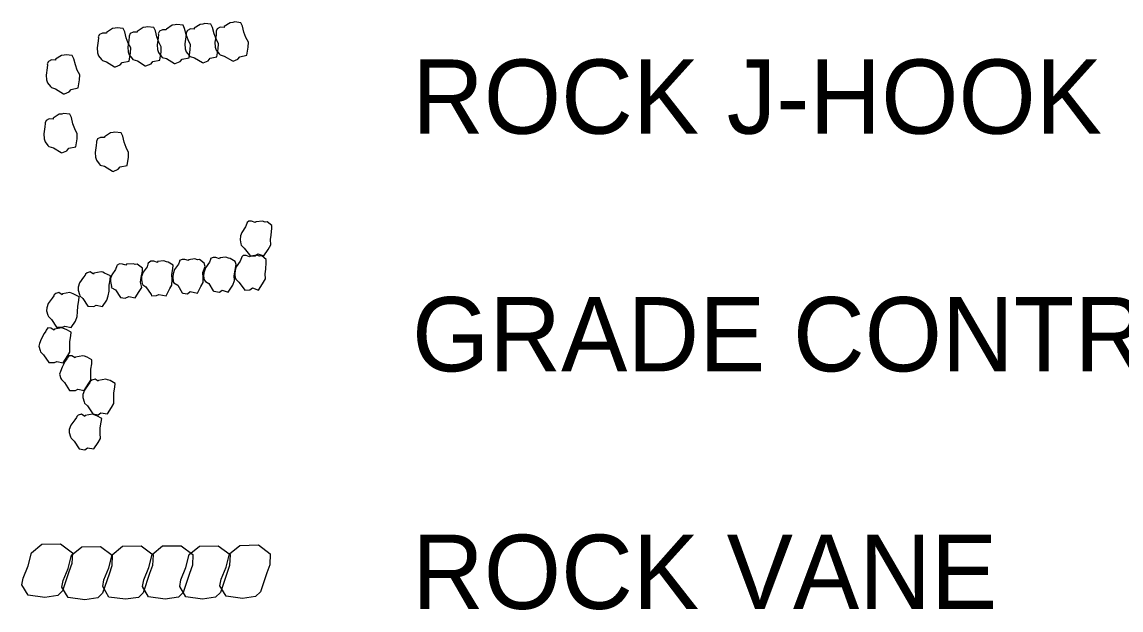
# Model space of a CAD drawing. Extents: x 1577194 to 26153757, y 723342 to 3772486.
# Drawn here: x 1577324.3 to 1577435.2, y 724614.4 to 724673.8 of the extents above; entities that cross this region are included whole.
import ezdxf

# ---------------------------------------------------------------- set-up
doc = ezdxf.new("R2010")
doc.units = 0
doc.layers.add('L-CL', color=7, linetype='Continuous')

msp = doc.modelspace()

# ---------------------------------------------------------------- linework, layer by layer
at = {"layer": 'L-CL'}
for p, q in [((1577339.66, 724669.6), (1577339.73, 724669.58)), ((1577342.48, 724669.68), (1577342.55, 724669.66)), ((1577345.5, 724669.85), (1577345.57, 724669.83)), ((1577333.62, 724669.27), (1577333.69, 724669.25)), ((1577336.71, 724669.37), (1577336.78, 724669.35)), ((1577328.47, 724666.54), (1577328.54, 724666.52)), ((1577328.23, 724660.6), (1577328.3, 724660.58)), ((1577333.41, 724658.73), (1577333.48, 724658.7)), ((1577347.24, 724650.26), (1577347.3, 724650.15)), ((1577337.29, 724646.26), (1577337.34, 724646.14)), ((1577340.42, 724646.44), (1577340.51, 724646.41)), ((1577343.55, 724646.63), (1577343.64, 724646.6)), ((1577346.69, 724646.81), (1577346.75, 724646.69)), ((1577330.92, 724645.07), (1577330.92, 724645.07)), ((1577334.21, 724645.95), (1577334.21, 724645.95)), ((1577327.76, 724642.97), (1577327.76, 724642.97)), ((1577326.96, 724639.39), (1577326.96, 724639.39)), ((1577329.07, 724636.58), (1577329.07, 724636.58)), ((1577331.4, 724634.22), (1577331.4, 724634.22)), ((1577330.04, 724630.68), (1577330.04, 724630.68))]:
    msp.add_line(p, q, dxfattribs=at)
for points in [[(1577333.69, 724669.25), (1577334.19, 724669.45), (1577334.39, 724669.7), (1577335.09, 724669.84), (1577335.21, 724670.67), (1577335.24, 724671.16), (1577334.99, 724671.66), (1577334.79, 724672.18), (1577334.64, 724672.8), (1577334.48, 724673.13), (1577333.86, 724673.21), (1577333.67, 724673.16), (1577333.39, 724673.13), (1577332.79, 724672.74), (1577332.78, 724672.65), (1577332.4, 724672.67), (1577332.1, 724672.52), (1577331.97, 724672.27), (1577331.98, 724672.19), (1577331.96, 724671.87), (1577331.85, 724671.16), (1577331.89, 724670.67), (1577331.99, 724670.36), (1577332.28, 724669.99), (1577332.38, 724669.89), (1577332.81, 724669.76), (1577333.62, 724669.27)], [(1577336.78, 724669.35), (1577337.29, 724669.55), (1577337.48, 724669.8), (1577338.18, 724669.94), (1577338.3, 724670.76), (1577338.33, 724671.26), (1577338.09, 724671.75), (1577337.89, 724672.28), (1577337.73, 724672.9), (1577337.57, 724673.23), (1577336.95, 724673.31), (1577336.77, 724673.26), (1577336.49, 724673.22), (1577335.89, 724672.84), (1577335.88, 724672.75), (1577335.49, 724672.77), (1577335.2, 724672.62), (1577335.07, 724672.37), (1577335.08, 724672.28), (1577335.06, 724671.96), (1577334.95, 724671.25), (1577334.98, 724670.77), (1577335.09, 724670.46), (1577335.37, 724670.09), (1577335.47, 724669.98), (1577335.91, 724669.86), (1577336.71, 724669.37)], [(1577339.73, 724669.58), (1577340.24, 724669.78), (1577340.43, 724670.03), (1577341.14, 724670.17), (1577341.25, 724670.99), (1577341.28, 724671.49), (1577341.04, 724671.98), (1577340.84, 724672.51), (1577340.68, 724673.13), (1577340.52, 724673.46), (1577339.9, 724673.54), (1577339.72, 724673.49), (1577339.44, 724673.46), (1577338.84, 724673.07), (1577338.83, 724672.98), (1577338.44, 724673), (1577338.15, 724672.85), (1577338.02, 724672.6), (1577338.03, 724672.52), (1577338.01, 724672.2), (1577337.9, 724671.49), (1577337.93, 724671), (1577338.04, 724670.69), (1577338.32, 724670.32), (1577338.42, 724670.21), (1577338.86, 724670.09), (1577339.66, 724669.6)], [(1577342.55, 724669.66), (1577343.05, 724669.86), (1577343.25, 724670.12), (1577343.95, 724670.25), (1577344.07, 724671.08), (1577344.1, 724671.58), (1577343.85, 724672.07), (1577343.65, 724672.6), (1577343.5, 724673.22), (1577343.34, 724673.55), (1577342.72, 724673.62), (1577342.53, 724673.58), (1577342.25, 724673.54), (1577341.65, 724673.16), (1577341.64, 724673.07), (1577341.26, 724673.08), (1577340.96, 724672.94), (1577340.83, 724672.69), (1577340.84, 724672.6), (1577340.82, 724672.28), (1577340.71, 724671.57), (1577340.75, 724671.09), (1577340.85, 724670.78), (1577341.14, 724670.4), (1577341.24, 724670.3), (1577341.67, 724670.17), (1577342.48, 724669.68)], [(1577345.57, 724669.83), (1577346.07, 724670.03), (1577346.27, 724670.28), (1577346.97, 724670.42), (1577347.09, 724671.24), (1577347.12, 724671.74), (1577346.87, 724672.23), (1577346.67, 724672.76), (1577346.52, 724673.38), (1577346.36, 724673.71), (1577345.74, 724673.79), (1577345.55, 724673.74), (1577345.28, 724673.71), (1577344.67, 724673.32), (1577344.67, 724673.23), (1577344.28, 724673.25), (1577343.98, 724673.1), (1577343.85, 724672.85), (1577343.86, 724672.77), (1577343.85, 724672.45), (1577343.73, 724671.74), (1577343.77, 724671.25), (1577343.87, 724670.94), (1577344.16, 724670.57), (1577344.26, 724670.46), (1577344.69, 724670.34), (1577345.5, 724669.85)], [(1577328.54, 724666.52), (1577329.04, 724666.73), (1577329.24, 724666.98), (1577329.94, 724667.12), (1577330.06, 724667.94), (1577330.09, 724668.44), (1577329.84, 724668.93), (1577329.65, 724669.46), (1577329.49, 724670.08), (1577329.33, 724670.41), (1577328.71, 724670.48), (1577328.52, 724670.43), (1577328.25, 724670.4), (1577327.65, 724670.02), (1577327.64, 724669.93), (1577327.25, 724669.95), (1577326.95, 724669.8), (1577326.82, 724669.55), (1577326.83, 724669.46), (1577326.82, 724669.14), (1577326.7, 724668.43), (1577326.74, 724667.95), (1577326.85, 724667.64), (1577327.13, 724667.26), (1577327.23, 724667.16), (1577327.66, 724667.03), (1577328.47, 724666.54)], [(1577328.3, 724660.58), (1577328.8, 724660.78), (1577329, 724661.03), (1577329.7, 724661.17), (1577329.82, 724661.99), (1577329.85, 724662.49), (1577329.61, 724662.99), (1577329.41, 724663.51), (1577329.25, 724664.13), (1577329.09, 724664.46), (1577328.47, 724664.54), (1577328.28, 724664.49), (1577328.01, 724664.46), (1577327.41, 724664.07), (1577327.4, 724663.98), (1577327.01, 724664), (1577326.71, 724663.85), (1577326.59, 724663.6), (1577326.59, 724663.52), (1577326.58, 724663.2), (1577326.47, 724662.49), (1577326.5, 724662), (1577326.61, 724661.69), (1577326.89, 724661.32), (1577326.99, 724661.22), (1577327.43, 724661.09), (1577328.23, 724660.6)], [(1577333.48, 724658.7), (1577333.98, 724658.91), (1577334.18, 724659.16), (1577334.88, 724659.3), (1577335, 724660.12), (1577335.03, 724660.62), (1577334.79, 724661.11), (1577334.59, 724661.64), (1577334.43, 724662.26), (1577334.27, 724662.59), (1577333.65, 724662.66), (1577333.47, 724662.61), (1577333.19, 724662.58), (1577332.59, 724662.2), (1577332.58, 724662.11), (1577332.19, 724662.12), (1577331.9, 724661.98), (1577331.77, 724661.73), (1577331.78, 724661.64), (1577331.76, 724661.32), (1577331.65, 724660.61), (1577331.68, 724660.13), (1577331.79, 724659.82), (1577332.07, 724659.45), (1577332.17, 724659.34), (1577332.61, 724659.21), (1577333.41, 724658.73)], [(1577347.3, 724650.15), (1577347.8, 724650.17), (1577348.07, 724650.37), (1577348.69, 724650.15), (1577349.11, 724650.8), (1577349.38, 724651.29), (1577349.36, 724651.8), (1577349.43, 724652.27), (1577349.47, 724652.95), (1577349.47, 724653.24), (1577349.01, 724653.6), (1577348.8, 724653.58), (1577348.54, 724653.67), (1577347.91, 724653.59), (1577347.79, 724653.53), (1577347.44, 724653.66), (1577347.15, 724653.66), (1577347, 724653.52), (1577346.97, 724653.43), (1577346.84, 724653.08), (1577346.45, 724652.52), (1577346.33, 724652.17), (1577346.29, 724651.79), (1577346.34, 724651.37), (1577346.4, 724651.25), (1577346.69, 724650.95), (1577347.24, 724650.26)], [(1577337.34, 724646.14), (1577337.85, 724646.16), (1577338.08, 724646.27), (1577338.82, 724646.11), (1577339.19, 724646.87), (1577339.4, 724647.2), (1577339.41, 724647.79), (1577339.39, 724648.29), (1577339.48, 724648.85), (1577339.52, 724649.23), (1577339.02, 724649.51), (1577338.85, 724649.57), (1577338.58, 724649.66), (1577337.96, 724649.58), (1577337.93, 724649.49), (1577337.58, 724649.62), (1577337.28, 724649.62), (1577337.01, 724649.42), (1577336.98, 724649.33), (1577336.89, 724649.07), (1577336.5, 724648.51), (1577336.34, 724648.07), (1577336.34, 724647.78), (1577336.39, 724647.36), (1577336.45, 724647.24), (1577336.77, 724647.03), (1577337.29, 724646.26)], [(1577340.51, 724646.41), (1577340.98, 724646.34), (1577341.25, 724646.55), (1577341.98, 724646.39), (1577342.32, 724647.06), (1577342.56, 724647.47), (1577342.54, 724647.97), (1577342.52, 724648.48), (1577342.74, 724649.09), (1577342.65, 724649.42), (1577342.19, 724649.78), (1577341.98, 724649.75), (1577341.72, 724649.85), (1577341.09, 724649.77), (1577341.06, 724649.68), (1577340.71, 724649.8), (1577340.42, 724649.81), (1577340.18, 724649.69), (1577340.15, 724649.61), (1577340.05, 724649.34), (1577339.66, 724648.79), (1577339.51, 724648.35), (1577339.5, 724648.05), (1577339.52, 724647.55), (1577339.58, 724647.43), (1577339.99, 724647.19), (1577340.42, 724646.44)], [(1577343.64, 724646.6), (1577344.2, 724646.5), (1577344.47, 724646.7), (1577345.09, 724646.48), (1577345.54, 724647.22), (1577345.7, 724647.66), (1577345.68, 724648.16), (1577345.77, 724648.72), (1577345.87, 724649.28), (1577345.79, 724649.6), (1577345.29, 724649.88), (1577345.11, 724649.94), (1577344.85, 724650.03), (1577344.23, 724649.95), (1577344.2, 724649.87), (1577343.84, 724649.99), (1577343.55, 724649.99), (1577343.31, 724649.88), (1577343.28, 724649.79), (1577343.19, 724649.53), (1577342.79, 724648.97), (1577342.61, 724648.44), (1577342.6, 724648.15), (1577342.66, 724647.73), (1577342.8, 724647.58), (1577343.12, 724647.37), (1577343.55, 724646.63)], [(1577346.75, 724646.69), (1577347.25, 724646.72), (1577347.52, 724646.92), (1577348.13, 724646.7), (1577348.56, 724647.34), (1577348.83, 724647.84), (1577348.81, 724648.34), (1577348.88, 724648.82), (1577348.92, 724649.49), (1577348.92, 724649.79), (1577348.46, 724650.15), (1577348.25, 724650.13), (1577347.98, 724650.22), (1577347.36, 724650.14), (1577347.24, 724650.08), (1577346.89, 724650.21), (1577346.6, 724650.21), (1577346.45, 724650.07), (1577346.41, 724649.98), (1577346.29, 724649.63), (1577345.9, 724649.07), (1577345.77, 724648.72), (1577345.74, 724648.33), (1577345.79, 724647.92), (1577345.85, 724647.8), (1577346.14, 724647.5), (1577346.69, 724646.81)], [(1577330.92, 724645.07), (1577331.52, 724645.06), (1577331.75, 724645.17), (1577332.4, 724645.04), (1577332.83, 724645.68), (1577332.98, 724646.12), (1577333.05, 724646.6), (1577333.06, 724647.19), (1577333.15, 724647.75), (1577333.19, 724648.13), (1577332.6, 724648.43), (1577332.43, 724648.5), (1577332.25, 724648.56), (1577331.51, 724648.42), (1577331.48, 724648.33), (1577331.16, 724648.55), (1577330.83, 724648.46), (1577330.68, 724648.32), (1577330.65, 724648.23), (1577330.47, 724648), (1577330.08, 724647.44), (1577329.92, 724647), (1577329.92, 724646.71), (1577330.06, 724646.26), (1577330.12, 724646.14), (1577330.41, 724645.84), (1577330.92, 724645.07)], [(1577334.21, 724645.95), (1577334.68, 724645.88), (1577335.04, 724646.06), (1577335.69, 724645.93), (1577336.11, 724646.57), (1577336.35, 724646.98), (1577336.24, 724647.51), (1577336.31, 724647.98), (1577336.44, 724648.63), (1577336.44, 724648.93), (1577335.89, 724649.32), (1577335.68, 724649.29), (1577335.51, 724649.36), (1577334.8, 724649.31), (1577334.76, 724649.22), (1577334.41, 724649.34), (1577334.12, 724649.35), (1577333.88, 724649.24), (1577333.85, 724649.15), (1577333.72, 724648.79), (1577333.33, 724648.24), (1577333.21, 724647.89), (1577333.2, 724647.59), (1577333.31, 724647.06), (1577333.28, 724646.97), (1577333.69, 724646.73), (1577334.21, 724645.95)], [(1577327.76, 724642.97), (1577328.35, 724642.96), (1577328.59, 724643.07), (1577329.24, 724642.94), (1577329.66, 724643.58), (1577329.82, 724644.03), (1577329.88, 724644.5), (1577329.89, 724645.09), (1577329.99, 724645.65), (1577330.03, 724646.03), (1577329.44, 724646.34), (1577329.26, 724646.4), (1577329.09, 724646.46), (1577328.35, 724646.32), (1577328.32, 724646.24), (1577327.99, 724646.45), (1577327.67, 724646.36), (1577327.52, 724646.22), (1577327.49, 724646.13), (1577327.31, 724645.9), (1577326.91, 724645.34), (1577326.76, 724644.9), (1577326.75, 724644.61), (1577326.89, 724644.16), (1577326.95, 724644.04), (1577327.24, 724643.74), (1577327.76, 724642.97)], [(1577326.96, 724639.39), (1577327.55, 724639.38), (1577327.78, 724639.5), (1577328.43, 724639.37), (1577328.89, 724640.1), (1577329.1, 724640.42), (1577329.11, 724641.01), (1577329.09, 724641.51), (1577329.18, 724642.07), (1577329.22, 724642.46), (1577328.72, 724642.73), (1577328.46, 724642.82), (1577328.28, 724642.89), (1577327.54, 724642.75), (1577327.51, 724642.66), (1577327.19, 724642.87), (1577326.89, 724642.88), (1577326.71, 724642.65), (1577326.68, 724642.56), (1577326.5, 724642.32), (1577326.2, 724641.74), (1577326.04, 724641.3), (1577325.95, 724641.03), (1577326.09, 724640.59), (1577326.15, 724640.47), (1577326.44, 724640.17), (1577326.96, 724639.39)], [(1577329.07, 724636.58), (1577329.66, 724636.57), (1577329.9, 724636.69), (1577330.55, 724636.56), (1577331, 724637.29), (1577331.21, 724637.61), (1577331.22, 724638.2), (1577331.2, 724638.71), (1577331.3, 724639.27), (1577331.33, 724639.65), (1577330.84, 724639.92), (1577330.57, 724640.02), (1577330.4, 724640.08), (1577329.66, 724639.94), (1577329.62, 724639.85), (1577329.3, 724640.07), (1577329.01, 724640.07), (1577328.83, 724639.84), (1577328.8, 724639.75), (1577328.62, 724639.52), (1577328.31, 724638.93), (1577328.16, 724638.49), (1577328.06, 724638.23), (1577328.2, 724637.78), (1577328.26, 724637.66), (1577328.55, 724637.36), (1577329.07, 724636.58)], [(1577331.4, 724634.22), (1577331.96, 724634.12), (1577332.23, 724634.32), (1577332.88, 724634.2), (1577333.3, 724634.84), (1577333.55, 724635.25), (1577333.53, 724635.75), (1577333.53, 724636.34), (1577333.63, 724636.9), (1577333.67, 724637.28), (1577333.17, 724637.56), (1577332.91, 724637.65), (1577332.73, 724637.71), (1577331.99, 724637.58), (1577331.96, 724637.49), (1577331.64, 724637.7), (1577331.31, 724637.62), (1577331.16, 724637.47), (1577331.13, 724637.38), (1577330.95, 724637.15), (1577330.56, 724636.6), (1577330.4, 724636.16), (1577330.4, 724635.86), (1577330.54, 724635.42), (1577330.59, 724635.3), (1577330.88, 724635), (1577331.4, 724634.22)], [(1577330.04, 724630.68), (1577330.6, 724630.58), (1577330.87, 724630.78), (1577331.52, 724630.66), (1577331.94, 724631.3), (1577332.18, 724631.71), (1577332.16, 724632.21), (1577332.17, 724632.8), (1577332.27, 724633.36), (1577332.31, 724633.74), (1577331.81, 724634.02), (1577331.54, 724634.11), (1577331.37, 724634.17), (1577330.63, 724634.04), (1577330.6, 724633.95), (1577330.27, 724634.16), (1577329.95, 724634.08), (1577329.8, 724633.93), (1577329.77, 724633.84), (1577329.59, 724633.61), (1577329.19, 724633.06), (1577329.04, 724632.61), (1577329.03, 724632.32), (1577329.17, 724631.87), (1577329.23, 724631.76), (1577329.52, 724631.46), (1577330.04, 724630.68)], [(1577324.39, 724617.61), (1577324.89, 724618.84), (1577325.22, 724620.16), (1577326.27, 724621.03), (1577328.16, 724621.06), (1577329.35, 724620.16), (1577329.3, 724619.08), (1577329.01, 724618.26), (1577328.36, 724616.32), (1577327.88, 724615.85), (1577326.56, 724615.67), (1577326.56, 724615.67), (1577324.88, 724615.89), (1577324.26, 724616.94), (1577324.39, 724617.61)], [(1577328.43, 724617.37), (1577328.93, 724618.6), (1577329.26, 724619.92), (1577330.3, 724620.79), (1577332.19, 724620.82), (1577333.38, 724619.92), (1577333.34, 724618.84), (1577333.05, 724618.02), (1577332.4, 724616.08), (1577331.92, 724615.61), (1577330.6, 724615.43), (1577330.6, 724615.43), (1577328.92, 724615.64), (1577328.3, 724616.7), (1577328.43, 724617.37)], [(1577332.53, 724617.43), (1577333.04, 724618.66), (1577333.36, 724619.98), (1577334.41, 724620.85), (1577336.3, 724620.88), (1577337.49, 724619.98), (1577337.44, 724618.9), (1577337.15, 724618.08), (1577336.51, 724616.14), (1577336.02, 724615.67), (1577334.71, 724615.49), (1577334.71, 724615.49), (1577333.02, 724615.7), (1577332.41, 724616.76), (1577332.53, 724617.43)], [(1577336.56, 724617.44), (1577337.06, 724618.67), (1577337.39, 724620), (1577338.44, 724620.86), (1577340.32, 724620.89), (1577341.52, 724619.99), (1577341.47, 724618.91), (1577341.18, 724618.09), (1577340.53, 724616.16), (1577340.05, 724615.69), (1577338.73, 724615.5), (1577338.73, 724615.5), (1577337.05, 724615.72), (1577336.43, 724616.77), (1577336.56, 724617.44)], [(1577340.31, 724617.44), (1577340.82, 724618.67), (1577341.15, 724619.99), (1577342.19, 724620.85), (1577344.08, 724620.89), (1577345.27, 724619.99), (1577345.22, 724618.9), (1577344.94, 724618.09), (1577344.29, 724616.15), (1577343.8, 724615.68), (1577342.49, 724615.5), (1577342.49, 724615.5), (1577340.8, 724615.71), (1577340.19, 724616.77), (1577340.31, 724617.44)], [(1577344.36, 724617.5), (1577344.87, 724618.73), (1577345.2, 724620.06), (1577346.24, 724620.92), (1577348.13, 724620.96), (1577349.32, 724620.05), (1577349.28, 724618.97), (1577348.99, 724618.16), (1577348.34, 724616.22), (1577347.85, 724615.75), (1577346.54, 724615.56), (1577346.54, 724615.56), (1577344.86, 724615.78), (1577344.24, 724616.83), (1577344.36, 724617.5)]]:
    msp.add_lwpolyline(points, dxfattribs=at)

# ---------------------------------------------------------------- texts
for s, p in [('ROCK J-HOOK', (1577363.64, 724662.5)), ('GRADE CONTROL ROCK J-HOOK', (1577363.64, 724638.5)), ('ROCK VANE', (1577363.64, 724614.5))]:
    msp.add_text(s, height=7.5, dxfattribs=at).set_placement(p)

doc.saveas('drawing.dxf')
